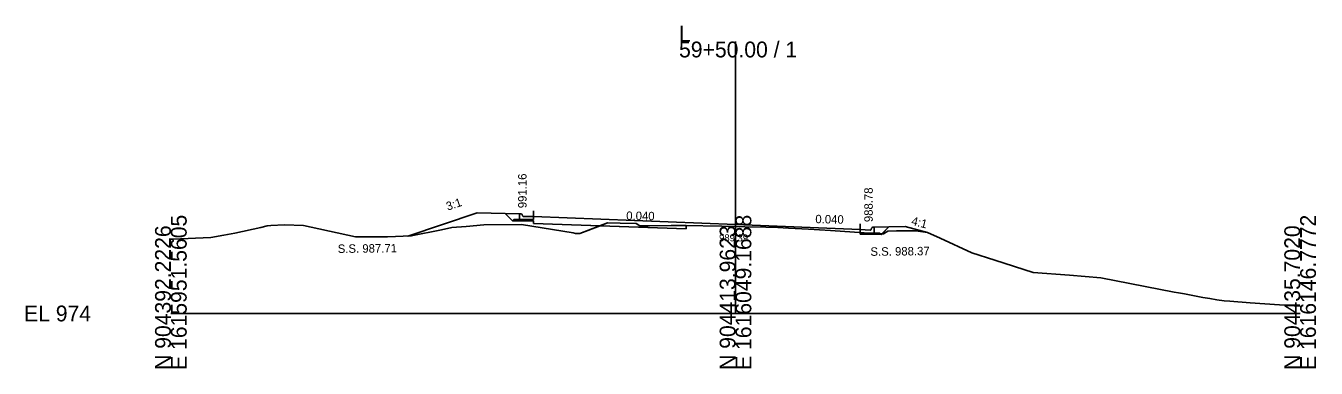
# Model space of a CAD drawing. Extents: x 1009 to 7438, y -1586 to 7964.
# Drawn here: x 5009.2 to 5237.7, y 7414 to 7474.7 of the extents above; entities that cross this region are included whole.
import ezdxf

# ---------------------------------------------------------------- set-up
doc = ezdxf.new("R2010")
doc.units = 0
for name, color, linetype in [('Exist Cross Section Cell', 7, 'Continuous'), ('Exist XS Center Line Elevation Label', 7, 'Continuous'), ('Exist XS Ground Line', 7, 'Continuous'), ('Prop XS Earthwork Shape', 7, 'Continuous'), ('Prop XS EOT Tick Mark', 7, 'Continuous'), ('Prop XS Finish Grade', 7, 'Continuous'), ('Prop XS Finish Grade CurbGutter', 7, 'Continuous'), ('Prop XS Finish Grade Earthwork', 7, 'Continuous'), ('Prop XS Finish Grade Pavement', 7, 'Continuous'), ('Prop XS Hydro Elevations', 7, 'Continuous'), ('Prop XS Pvmt Edge Slope', 7, 'Continuous'), ('Prop XS SE Text', 7, 'Continuous'), ('Prop XS Side Slope Text', 7, 'Continuous'), ('Prop XS SS Elevation Text', 7, 'Continuous'), ('Prop XS Subgrade CurbGutter', 7, 'Continuous'), ('Prop XS Subgrade Earthwork', 7, 'Continuous')]:
    doc.layers.add(name, color=color, linetype=linetype)

msp = doc.modelspace()

# ---------------------------------------------------------------- linework, layer by layer
at = {"layer": 'Exist Cross Section Cell'}
for p, q in [((5134.89, 7423.73), (5134.89, 7471.89)), ((5034.89, 7423.73), (5134.89, 7423.73)), ((5134.89, 7423.73), (5234.89, 7423.73))]:
    msp.add_line(p, q, dxfattribs=at)
at = {"layer": 'Exist XS Ground Line'}
for p, q in [((5046.22, 7437.96), (5050.82, 7438.94)), ((5050.82, 7438.94), (5051.96, 7439.28)), ((5051.96, 7439.28), (5052.58, 7439.32)), ((5052.58, 7439.32), (5054.99, 7439.46)), ((5054.99, 7439.46), (5058.37, 7439.33)), ((5058.37, 7439.33), (5059.72, 7439.03)), ((5059.72, 7439.03), (5067.6, 7437.31)), ((5082.82, 7438.56), (5084.68, 7438.95)), ((5084.68, 7438.95), (5087.19, 7439.16)), ((5087.19, 7439.16), (5090.32, 7439.41)), ((5090.32, 7439.41), (5096.99, 7439.48)), ((5096.99, 7439.48), (5106.16, 7437.99)), ((5107.34, 7437.88), (5112.23, 7439.78)), ((5112.23, 7439.78), (5114.49, 7439.74)), ((5114.49, 7439.74), (5117.28, 7439.65)), ((5117.28, 7439.65), (5117.95, 7439.23)), ((5117.95, 7439.23), (5118.89, 7439.27)), ((5118.89, 7439.27), (5119.68, 7439.28)), ((5119.68, 7439.28), (5123.51, 7439.3)), ((5123.51, 7439.3), (5125.81, 7439.29)), ((5125.81, 7439.29), (5132.44, 7439.18)), ((5132.44, 7439.18), (5134.89, 7439.12)), ((5134.89, 7439.12), (5136.56, 7439.09)), ((5136.56, 7439.09), (5140.28, 7439.01)), ((5140.28, 7439.01), (5142.38, 7438.98)), ((5142.38, 7438.98), (5144.27, 7438.87)), ((5144.27, 7438.87), (5147.83, 7438.66)), ((5034.89, 7436.89), (5035.23, 7436.9)), ((5035.23, 7436.9), (5041.99, 7437.19)), ((5041.99, 7437.19), (5044.25, 7437.63)), ((5044.25, 7437.63), (5046.22, 7437.96)), ((5067.6, 7437.31), (5071.46, 7437.3)), ((5071.46, 7437.3), (5072.58, 7437.3)), ((5072.58, 7437.3), (5073.23, 7437.32)), ((5073.23, 7437.32), (5077.47, 7437.46)), ((5077.47, 7437.46), (5082.82, 7438.56)), ((5106.16, 7437.99), (5106.57, 7437.92)), ((5106.57, 7437.92), (5107.34, 7437.88)), ((5147.83, 7438.66), (5151.7, 7438.4)), ((5151.7, 7438.4), (5159.41, 7437.9)), ((5159.41, 7437.9), (5160.59, 7437.85)), ((5160.59, 7437.85), (5161.11, 7437.85)), ((5161.11, 7437.85), (5161.85, 7438.31)), ((5161.85, 7438.31), (5163.41, 7438.34)), ((5163.41, 7438.34), (5166.83, 7438.36)), ((5166.83, 7438.36), (5168.87, 7438.1)), ((5168.87, 7438.1), (5171.12, 7437.06)), ((5171.12, 7437.06), (5176.75, 7434.45)), ((5176.75, 7434.45), (5180.81, 7433.2)), ((5180.81, 7433.2), (5187.6, 7431.01)), ((5187.6, 7431.01), (5194.05, 7430.53)), ((5194.05, 7430.53), (5199.59, 7430.02)), ((5199.59, 7430.02), (5212.58, 7427.53)), ((5212.58, 7427.53), (5213.37, 7427.39)), ((5213.37, 7427.39), (5214.42, 7427.23)), ((5214.42, 7427.23), (5217.67, 7426.57)), ((5217.67, 7426.57), (5218.9, 7426.38)), ((5218.9, 7426.38), (5220.16, 7426.13)), ((5220.16, 7426.13), (5221.43, 7425.99)), ((5221.43, 7425.99), (5222.44, 7425.91)), ((5222.44, 7425.91), (5226.01, 7425.59)), ((5226.01, 7425.59), (5231.22, 7425.25)), ((5231.22, 7425.25), (5233.85, 7425.09)), ((5233.85, 7425.09), (5234.89, 7425.02))]:
    msp.add_line(p, q, dxfattribs=at)
at = {"layer": 'Prop XS Earthwork Shape'}
for points in [[(5106.57, 7437.92), (5107.34, 7437.88), (5110.91, 7439.27), (5099.14, 7439.69), (5099.14, 7440.1), (5095.39, 7440.16), (5094.12, 7441.43), (5089.14, 7441.54), (5076.84, 7437.44), (5077.47, 7437.46), (5082.82, 7438.56), (5084.68, 7438.95), (5087.19, 7439.16), (5090.32, 7439.41), (5096.99, 7439.48), (5106.16, 7437.99)], [(5126.14, 7438.72), (5110.91, 7439.27), (5112.23, 7439.78), (5114.49, 7439.74), (5117.28, 7439.65), (5117.95, 7439.23), (5118.89, 7439.27), (5119.68, 7439.28), (5123.51, 7439.3), (5125.81, 7439.29), (5126.13, 7439.29)], [(5162.05, 7439.05), (5164.96, 7439.11), (5168.87, 7438.1), (5166.83, 7438.36), (5163.41, 7438.34), (5161.85, 7438.31), (5161.11, 7437.85), (5160.85, 7437.85)], [(5156.96, 7438.06), (5156.96, 7438.03), (5157.43, 7438.03)], [(5156.96, 7437.78), (5160.71, 7437.71), (5160.57, 7437.86), (5159.41, 7437.9), (5157.43, 7438.03), (5156.96, 7438.03)], [(5160.71, 7437.71), (5160.85, 7437.85), (5160.59, 7437.85), (5160.57, 7437.86)]]:
    msp.add_lwpolyline(points, close=True, dxfattribs=at)
at = {"layer": 'Prop XS EOT Tick Mark'}
for p, q in [((5099.14, 7440.93), (5099.14, 7441.93)), ((5156.96, 7438.6), (5156.96, 7439.6))]:
    msp.add_line(p, q, dxfattribs=at)
at = {"layer": 'Prop XS Finish Grade'}
for p, q in [((5096.64, 7441.38), (5094.12, 7441.43)), ((5159.46, 7438.99), (5162.05, 7439.05))]:
    msp.add_line(p, q, dxfattribs=at)
at = {"layer": 'Prop XS Finish Grade CurbGutter'}
for p, q in [((5096.64, 7441.38), (5096.89, 7441.38)), ((5096.89, 7441.38), (5097.02, 7441.34)), ((5097.11, 7441.25), (5097.02, 7441.34)), ((5097.18, 7441), (5097.11, 7441.25)), ((5097.27, 7440.91), (5097.18, 7441)), ((5097.39, 7440.89), (5097.27, 7440.91)), ((5099.14, 7440.93), (5097.39, 7440.89)), ((5158.93, 7438.62), (5158.99, 7438.87)), ((5158.99, 7438.87), (5159.09, 7438.97)), ((5159.21, 7438.99), (5159.09, 7438.97)), ((5159.46, 7438.99), (5159.21, 7438.99)), ((5156.96, 7438.61), (5158.71, 7438.51)), ((5158.71, 7438.51), (5158.84, 7438.53)), ((5158.84, 7438.53), (5158.93, 7438.62))]:
    msp.add_line(p, q, dxfattribs=at)
at = {"layer": 'Prop XS Finish Grade Earthwork'}
for p, q in [((5089.14, 7441.54), (5076.84, 7437.44)), ((5094.12, 7441.43), (5089.14, 7441.54)), ((5162.05, 7439.05), (5164.96, 7439.11)), ((5164.96, 7439.11), (5168.87, 7438.1))]:
    msp.add_line(p, q, dxfattribs=at)
at = {"layer": 'Prop XS Finish Grade Pavement'}
for p, q in [((5099.14, 7440.93), (5134.89, 7439.5)), ((5134.89, 7439.5), (5156.96, 7438.61))]:
    msp.add_line(p, q, dxfattribs=at)
at = {"layer": 'Prop XS Pvmt Edge Slope'}
for p, q in [((5095.64, 7440.4), (5095.39, 7440.16)), ((5096.64, 7440.39), (5095.64, 7440.4)), ((5159.46, 7437.98), (5160.46, 7437.96)), ((5160.46, 7437.96), (5160.71, 7437.71))]:
    msp.add_line(p, q, dxfattribs=at)
at = {"layer": 'Prop XS Subgrade CurbGutter'}
for p, q in [((5096.64, 7440.39), (5096.64, 7441.38)), ((5099.14, 7440.35), (5096.64, 7440.39)), ((5099.14, 7440.93), (5099.14, 7440.35)), ((5159.46, 7437.98), (5159.46, 7438.99)), ((5156.96, 7438.61), (5156.96, 7438.03)), ((5156.96, 7438.03), (5159.46, 7437.98))]:
    msp.add_line(p, q, dxfattribs=at)
at = {"layer": 'Prop XS Subgrade Earthwork'}
for p, q in [((5095.39, 7440.16), (5094.12, 7441.43)), ((5099.14, 7440.1), (5095.39, 7440.16)), ((5099.14, 7439.69), (5099.14, 7440.1)), ((5126.14, 7438.72), (5099.14, 7439.69)), ((5126.14, 7438.72), (5126.13, 7439.29)), ((5160.71, 7437.71), (5162.05, 7439.05)), ((5156.96, 7438.06), (5156.96, 7437.78)), ((5156.96, 7437.78), (5160.71, 7437.71))]:
    msp.add_line(p, q, dxfattribs=at)

# ---------------------------------------------------------------- texts
at = {"layer": 'Exist Cross Section Cell'}
for s, p in [('L', (5124.89, 7471.89)), ('59+50.00 / 1', (5124.89, 7469.09)), ('EL 974', (5008.89, 7422.33))]:
    msp.add_text(s, height=2.8, dxfattribs=at).set_placement(p)
for s, p in [('E 1615951.5605', (5037.69, 7413.73)), ('E 1616049.1688', (5137.69, 7413.73)), ('E 1616146.7772', (5237.69, 7413.73)), ('N 904392.2226', (5034.89, 7413.73)), ('N 904413.9623', (5134.89, 7413.73)), ('N 904435.7020', (5234.89, 7413.73))]:
    msp.add_text(s, height=2.8, rotation=90, dxfattribs=at).set_placement(p)
at = {"layer": 'Exist XS Center Line Elevation Label'}
msp.add_text('989.39', height=1.25, dxfattribs=at).set_placement((5131.99, 7436.5))
at = {"layer": 'Prop XS Hydro Elevations'}
for s, p in [('991.16', (5097.89, 7442.38)), ('988.78', (5159.2, 7439.91))]:
    msp.add_text(s, height=1.5, rotation=90, dxfattribs=at).set_placement(p)
at = {"layer": 'Prop XS SE Text'}
for rotation, p in [(359.0652, (5115.53, 7440.31)), (358.8542, (5149.02, 7439.72))]:
    msp.add_text('0.040', height=1.5, rotation=rotation, dxfattribs=at).set_placement(p)
at = {"layer": 'Prop XS Side Slope Text'}
for s, rotation, p in [('3:1', 18.4349, (5083.92, 7441.93)), ('4:1', 345.9638, (5165.93, 7439.46))]:
    msp.add_text(s, height=1.5, rotation=rotation, dxfattribs=at).set_placement(p)
at = {"layer": 'Prop XS SS Elevation Text'}
for s, p in [('S.S. 987.71', (5064.46, 7434.45)), ('S.S. 988.37', (5158.8, 7433.94))]:
    msp.add_text(s, height=1.5, rotation=0.5729, dxfattribs=at).set_placement(p)

doc.saveas('drawing.dxf')
